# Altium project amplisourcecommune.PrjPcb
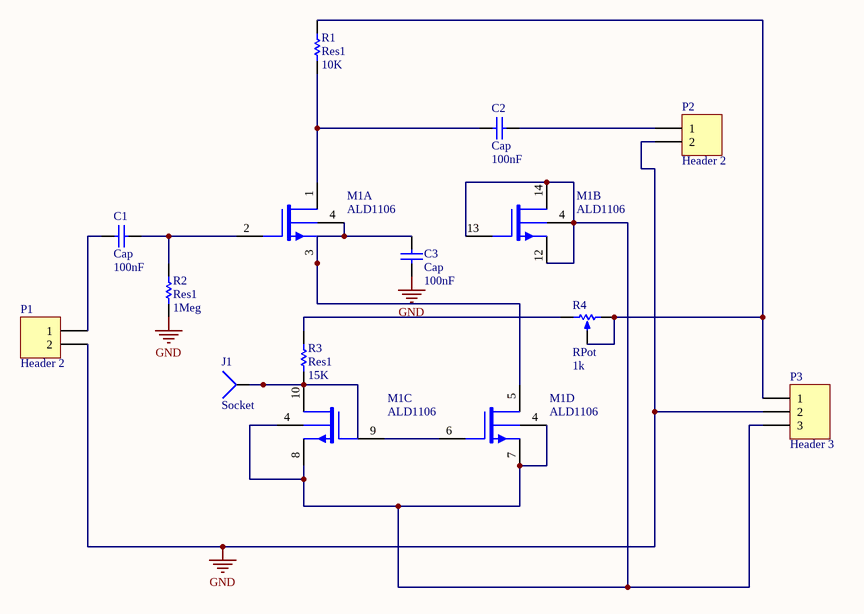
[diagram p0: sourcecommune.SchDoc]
1 sheet, 12 parts. Net scope: global (net labels, ports and power ports of the same name join across sheets).
Board file: PCB1.PcbDoc

## Sheet sourcecommune.SchDoc
size A4

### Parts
C1  Cap  value 100nF  [RAD-0.3]
C2  Cap  value 100nF  [RAD-0.3]
C3  Cap  value 100nF  [RAD-0.3]
J1  Socket  [PIN1]
M1  ALD1106  [DIP-14]  (parts A,B,C,D of 4)
P1  Header 2  [HDR1X2]
P2  Header 2  [HDR1X2]
P3  Header 3  [HDR1X3]
R1  Res1  value 10K  [AXIAL-0.3]
R2  Res1  value 1Meg  [AXIAL-0.3]
R3  Res1  value 15K  [AXIAL-0.3]
R4  RPot  value 1k  [VR5]

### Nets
GND: C3.1 P1.2 P2.2 P3.2 R2.1
NetC1_1: C1.1 P1.1
NetC1_2: C1.2 M1.2(GN1) R2.2
NetC2_1: C2.1 M1.1(DN1) R1.1
NetC2_2: C2.2 P2.1
NetC3_2: C3.2 M1.3(SN1) M1.4(V-) M1.5(DN4)
NetJ1_1: J1.1 M1.10(DN3) R3.1
NetM1_4: M1.4(V-) M1.7(SN4) M1.8(SN3) M1.12(SN2) M1.13(GN2) M1.14(DN2) P3.3
NetM1_6: M1.6(GN4) M1.9(GN3)
NetP3_1: P3.1 R1.2 R4.2(TAP) R4.3(BOT)
NetR3_2: R3.2 R4.1(TOP)

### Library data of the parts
C1-C3 = Cap: Capacitor
M1 = ALD1106: Quad N-channel matched MOSFET array
P1 P2 = Header 2: Header, 2-Pin
P3 = Header 3: Header, 3-Pin
R1-R3 = Res1: Resistor
R4 = RPot: Potentiometer; Sim Note: Enter the Resistance value and the set point into parameter fields.; Set Position: 0.5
